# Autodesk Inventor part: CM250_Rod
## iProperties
Author: ovrein
Created: 2001-03
Part Number: CM250_Rod
Material: S355J2G3
Document SubType Name: Modeling
Designer: ovrein
Control State: 0
Master: False
Checked Out: False
Last Check In Date: 2001-07-27
PropertySet Name: Design Tracking Control
Last Check In By: ovrein
Shininess: 41.0
PropertySet Name: _Private Model Information
Density: 0.0
Volumn: 0.0
Area: 0.0
PropertySet Name: Model Information
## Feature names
1. Extrusion1
2. Extrusion2
3. Extrusion3
4. Extrusion4
5. Chamfer1
6. Fillet1
